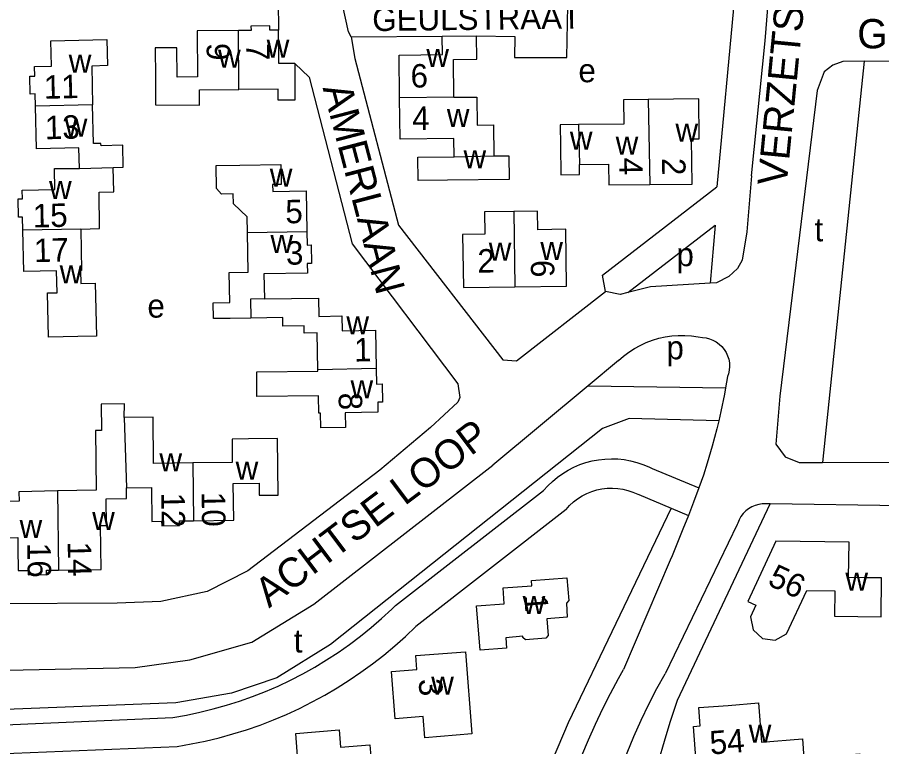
# Model space of a CAD drawing. Extents: x 156721 to 158827, y 386657 to 388950.
# Drawn here: x 158105.4 to 158252.9, y 387600.8 to 387725.3 of the extents above; entities that cross this region are included whole.
import ezdxf

# ---------------------------------------------------------------- set-up
doc = ezdxf.new("R2010")
doc.units = 0
for name, color, linetype in [('BLT_Basislijn', 7, 'Continuous'), ('BLT_Bebouwing', 7, 'Continuous'), ('BLT_Centroide', 7, 'Continuous'), ('BLT_Huisnummer', 7, 'Continuous'), ('BLT_Huisnummer_ tussenligend', 7, 'Continuous'), ('BLT_Onderverdeling_panden', 7, 'Continuous'), ('BLT_Straatnaam', 7, 'Continuous'), ('BLT_Straatnaam_verkleind', 7, 'Continuous')]:
    doc.layers.add(name, color=color, linetype=linetype)

msp = doc.modelspace()

# ---------------------------------------------------------------- linework, layer by layer
at = {"layer": 'BLT_Basislijn'}
for p, q in [((158229.04, 387741.65), (158224.79, 387696.34)), ((158149.92, 387727.95), (158149.97, 387723.07)), ((158162.37, 387721.93), (158177.92, 387722.06)), ((158249.95, 387717.76), (158242.83, 387649.3)), ((158152.75, 387717.41), (158155.18, 387715.03)), ((158155.18, 387715.03), (158162.54, 387686.61)), ((158205.28, 387681.26), (158224.79, 387696.34)), ((158209.61, 387678.29), (158224.52, 387689.81)), ((158224.52, 387689.81), (158223.65, 387679.92)), ((158162.54, 387686.61), (158180.58, 387662.74)), ((158205.81, 387678.51), (158205.28, 387681.26)), ((158208.02, 387666.72), (158202.82, 387662.39)), ((158226.63, 387663.98), (158226.28, 387662.04)), ((158180.58, 387662.74), (158180.9, 387660.42)), ((158202.82, 387662.39), (158186.53, 387648.84)), ((158202.82, 387662.39), (158226.28, 387662.04)), ((158180.9, 387660.42), (158180.58, 387659.62)), ((158180.58, 387659.62), (158175.92, 387655.3)), ((158175.92, 387655.3), (158167.26, 387648.03)), ((158213.75, 387648.27), (158221.71, 387644.99)), ((158167.26, 387648.03), (158144.75, 387630.82)), ((158222.52, 387647.14), (158221.71, 387644.99)), ((158169.91, 387624.92), (158195.21, 387644.52)), ((158211.46, 387643.83), (158216.97, 387641.54)), ((158218.09, 387608.76), (158233.87, 387642.27)), ((158233.87, 387642.27), (158233.18, 387642.28)), ((158270.59, 387641.69), (158233.87, 387642.27)), ((158199.05, 387641.32), (158173.42, 387621.35)), ((158216.97, 387641.54), (158207.52, 387621.83)), ((158216.97, 387641.54), (158219.93, 387640.3)), ((158228.28, 387638.75), (158215.94, 387613.27)), ((158216.84, 387632.65), (158208.88, 387613.99)), ((158144.75, 387630.82), (158137.79, 387627.31)), ((158137.79, 387627.31), (158129.87, 387625.61)), ((158122.4, 387625.3), (158078.39, 387625.06)), ((158129.87, 387625.61), (158122.4, 387625.3)), ((158207.52, 387621.83), (158199.39, 387604.87)), ((158093.22, 387604.12), (158131.92, 387605.82)), ((158199.39, 387604.87), (158196.7, 387598.46)), ((158095.31, 387599.32), (158132.68, 387600.88))]:
    msp.add_line(p, q, dxfattribs=at)
for points in [[(158230.7, 387698.25), (158233.04, 387721.24), (158234.67, 387741.75)], [(158162.37, 387721.93), (158161.92, 387722.8), (158160.89, 387727.45)], [(158183.78, 387722.13), (158190.28, 387721.98), (158190.27, 387718.43), (158199.18, 387718.42), (158199.34, 387727.31)], [(158162.37, 387721.93), (158162.99, 387718.25), (158170.46, 387689.82), (158188.23, 387666.84), (158190.61, 387666.68), (158205.81, 387678.51)], [(158249.95, 387717.76), (158246.27, 387717.74), (158244.57, 387717.09), (158243.09, 387715.96), (158241.94, 387712.8), (158235.53, 387660.62), (158234.87, 387652.44), (158236.45, 387650.27), (158238.86, 387649.33), (158242.83, 387649.3)], [(158331.61, 387684.16), (158329.92, 387691.11), (158327.69, 387713.57), (158325.62, 387716.63), (158322.75, 387717.43), (158319.65, 387717.59), (158249.95, 387717.76)], [(158230.7, 387698.25), (158229.92, 387688.65), (158229.12, 387683.83), (158228.32, 387682.39), (158226.84, 387681.07), (158224.73, 387679.99), (158223.65, 387679.92)], [(158331.61, 387684.16), (158330.27, 387682.97), (158337.29, 387598.34), (158342.49, 387594.21), (158431.88, 387594.8), (158432.5, 387594.66), (158434.94, 387592.24), (158434.85, 387566.34), (158432.92, 387555.36), (158430.15, 387548.17), (158421.36, 387530.67), (158420.31, 387528.76), (158417.02, 387526.27), (158293.15, 387534.97), (158290, 387537.72), (158280.9, 387649.05), (158280.63, 387649.25), (158242.83, 387649.3)], [(158223.65, 387679.92), (158213.47, 387679.26), (158209.61, 387678.29)], [(158209.61, 387678.29), (158208.3, 387677.96), (158205.81, 387678.51)], [(158208.02, 387666.72), (158208.88, 387667.46), (158209.78, 387668.14), (158210.72, 387668.76), (158211.71, 387669.3), (158212.74, 387669.77), (158213.79, 387670.17), (158214.87, 387670.5), (158215.97, 387670.74), (158217.09, 387670.91), (158218.21, 387671), (158219.34, 387671.01), (158220.47, 387670.93), (158221.59, 387670.78), (158222.32, 387670.64)], [(158222.32, 387670.64), (158222.94, 387670.57), (158223.55, 387670.42), (158224.13, 387670.19), (158224.68, 387669.89), (158225.19, 387669.52), (158225.64, 387669.1), (158226.04, 387668.61), (158226.37, 387668.08), (158226.63, 387667.52), (158226.82, 387666.92), (158226.93, 387666.3), (158226.96, 387665.68), (158226.91, 387665.05), (158226.78, 387664.44), (158226.63, 387663.98)], [(158226.28, 387662.04), (158226.09, 387660.99), (158225.47, 387658.01), (158225.1, 387656.4)], [(158225.1, 387656.4), (158209.8, 387656.83), (158205.26, 387655.11), (158158.86, 387618.27), (158149.7, 387612.59), (158141.94, 387609.97), (158132.46, 387608.3), (158098.96, 387606.99)], [(158225.1, 387656.4), (158224.78, 387655.05), (158224.01, 387652.1), (158223.16, 387649.18), (158222.52, 387647.14)], [(158195.21, 387644.52), (158195.94, 387645.34), (158196.74, 387646.1), (158197.58, 387646.8), (158198.48, 387647.44), (158199.42, 387648.02), (158200.39, 387648.52), (158201.4, 387648.95), (158202.45, 387649.31), (158203.51, 387649.59), (158204.59, 387649.79), (158205.68, 387649.91), (158206.78, 387649.95), (158207.88, 387649.92), (158208.98, 387649.8), (158210.06, 387649.6), (158211.12, 387649.33), (158212.16, 387648.98), (158213.18, 387648.55), (158213.75, 387648.27)], [(158095.39, 387613.72), (158125.49, 387614.36), (158134.85, 387615.64), (158145.39, 387618.65), (158155.99, 387625.14), (158186.53, 387648.84)], [(158199.05, 387641.32), (158199.65, 387641.98), (158200.32, 387642.59), (158201.03, 387643.13), (158201.79, 387643.61), (158202.59, 387644.03), (158203.43, 387644.37), (158204.29, 387644.63), (158205.17, 387644.82), (158206.06, 387644.92), (158206.96, 387644.95), (158207.86, 387644.9), (158208.75, 387644.77), (158209.62, 387644.56), (158210.47, 387644.27), (158211.3, 387643.91), (158211.46, 387643.83)], [(158221.71, 387644.99), (158220.8, 387642.52), (158219.93, 387640.3)], [(158233.18, 387642.28), (158232.55, 387642.27), (158231.93, 387642.17), (158231.33, 387642), (158230.76, 387641.75), (158230.22, 387641.43), (158229.72, 387641.04), (158229.28, 387640.6), (158228.9, 387640.1), (158228.59, 387639.55), (158228.35, 387638.98), (158228.28, 387638.75)], [(158219.93, 387640.3), (158219.01, 387637.94), (158217.15, 387633.38), (158216.84, 387632.65)], [(158131.92, 387605.82), (158134.24, 387606.22), (158136.54, 387606.7), (158138.83, 387607.26), (158141.09, 387607.89), (158143.33, 387608.6), (158145.55, 387609.38), (158147.74, 387610.24), (158149.9, 387611.18), (158152.03, 387612.18), (158154.12, 387613.26), (158156.17, 387614.41), (158158.18, 387615.63), (158160.15, 387616.92), (158162.08, 387618.27), (158163.96, 387619.69), (158165.79, 387621.17), (158167.56, 387622.71), (158169.29, 387624.31), (158169.91, 387624.92)], [(158132.68, 387600.88), (158135.08, 387601.29), (158137.47, 387601.78), (158139.84, 387602.35), (158142.19, 387603), (158144.51, 387603.72), (158146.81, 387604.52), (158149.09, 387605.39), (158151.33, 387606.34), (158153.55, 387607.36), (158155.72, 387608.46), (158157.86, 387609.62), (158159.96, 387610.85), (158162.02, 387612.16), (158164.04, 387613.52), (158166.01, 387614.96), (158167.93, 387616.46), (158169.8, 387618.02), (158171.62, 387619.64), (158173.42, 387621.35)], [(158194.39, 387559.31), (158194.4, 387562.23), (158194.49, 387565.15), (158194.67, 387568.07), (158194.92, 387570.98), (158195.25, 387573.88), (158195.66, 387576.78), (158196.15, 387579.66), (158196.73, 387582.52), (158197.37, 387585.37), (158198.1, 387588.21), (158198.9, 387591.01), (158199.78, 387593.8), (158200.74, 387596.56), (158201.77, 387599.3), (158202.87, 387602), (158204.05, 387604.68), (158205.3, 387607.32), (158206.63, 387609.92), (158208.02, 387612.49), (158208.88, 387613.99)], [(158201.24, 387552.3), (158201.17, 387555.33), (158201.17, 387558.37), (158201.24, 387561.4), (158201.4, 387564.43), (158201.64, 387567.45), (158201.96, 387570.47), (158202.36, 387573.48), (158202.84, 387576.47), (158203.4, 387579.46), (158204.03, 387582.42), (158204.74, 387585.37), (158205.54, 387588.3), (158206.4, 387591.21), (158207.35, 387594.09), (158208.37, 387596.95), (158209.46, 387599.77), (158210.63, 387602.57), (158211.87, 387605.34), (158213.19, 387608.07), (158214.57, 387610.77), (158215.94, 387613.27)], [(158210.06, 387568.18), (158210.28, 387571.59), (158210.58, 387574.99), (158210.96, 387578.39), (158211.43, 387581.78), (158211.96, 387585.15), (158212.58, 387588.51), (158213.28, 387591.85), (158214.06, 387595.18), (158214.91, 387598.49), (158215.84, 387601.78), (158216.84, 387605.04), (158217.93, 387608.28), (158218.09, 387608.76)]]:
    msp.add_lwpolyline(points, dxfattribs=at)
at = {"layer": 'BLT_Bebouwing'}
msp.add_line((158177.92, 387722.06), (158183.78, 387722.13), dxfattribs=at)
for points in [[(158149.97, 387723.07), (158148.47, 387723.06), (158148.46, 387723.8), (158145.27, 387723.78), (158145.28, 387723.02), (158143.14, 387723)], [(158143.14, 387723), (158136.1, 387722.96), (158136.14, 387715.09), (158132.65, 387715.07), (158132.62, 387720.08), (158128.93, 387720.06), (158128.95, 387715.06), (158128.98, 387710.33)], [(158152.75, 387717.41), (158150.01, 387717.39), (158149.97, 387723.07)], [(158170.64, 387711.51), (158170.55, 387718.83), (158177.96, 387718.92), (158177.92, 387722.06)], [(158179.9, 387711.63), (158179.82, 387718.06), (158183.83, 387718.11), (158183.78, 387722.13)], [(158108.46, 387710.1), (158108.41, 387712.2), (158107.6, 387712.18), (158107.53, 387715.23), (158108.36, 387715.25), (158108.32, 387716.87), (158111.22, 387716.94), (158111.12, 387721.26), (158120.67, 387721.49)], [(158120.67, 387721.49), (158120.78, 387717.02), (158118.09, 387716.95), (158118.24, 387710.34)], [(158152.75, 387717.41), (158152.78, 387711.13), (158149.92, 387711.11), (158149.91, 387712.99), (158143.2, 387712.95)], [(158128.98, 387710.33), (158136.49, 387710.28), (158136.48, 387712.91), (158143.2, 387712.95)], [(158179.9, 387711.63), (158183.82, 387711.67), (158183.87, 387706.88), (158186.68, 387706.91), (158186.74, 387701.63)], [(158115.98, 387699.49), (158115.9, 387702.99), (158108.63, 387702.82), (158108.46, 387710.1)], [(158121.77, 387699.67), (158123.46, 387699.71), (158123.37, 387703.43), (158119.67, 387703.34), (158119.66, 387703.75), (158118.4, 387703.72), (158118.24, 387710.34)], [(158179.95, 387701.47), (158179.91, 387704.58), (158170.72, 387704.47), (158170.64, 387711.51)], [(158213.07, 387711.26), (158208.85, 387711.21), (158208.89, 387707.04), (158201.16, 387706.96)], [(158213.33, 387696.73), (158220.55, 387696.81), (158220.46, 387704.53), (158221.76, 387704.54), (158221.69, 387711.35), (158213.07, 387711.26)], [(158201.16, 387706.96), (158198.05, 387706.93), (158198.08, 387703.4), (158198.14, 387698.4), (158201.37, 387698.43), (158201.36, 387700.15)], [(158186.74, 387701.63), (158189.3, 387701.66), (158189.35, 387697.59), (158178.79, 387697.46), (158173.79, 387697.4), (158173.74, 387701.4), (158179.95, 387701.47)], [(158139.33, 387699.96), (158143.36, 387700.04), (158150.36, 387700.17), (158150.42, 387696.77), (158148.96, 387696.75), (158148.98, 387695.55), (158154.69, 387695.64), (158154.81, 387688.74)], [(158144.66, 387688.57), (158144.61, 387691.21), (158142.28, 387693.43), (158142.25, 387695.14), (158140.23, 387695.09), (158139.36, 387696.04), (158139.33, 387699.96)], [(158201.36, 387700.15), (158206.31, 387700.2), (158206.35, 387696.66), (158213.33, 387696.73)], [(158106.34, 387688.96), (158106.29, 387691.18), (158105.57, 387691.16), (158105.5, 387694.28), (158106.25, 387694.3), (158106.22, 387695.77), (158111.81, 387695.9), (158111.73, 387699.49), (158115.98, 387699.49)], [(158119.33, 387695.46), (158121.87, 387695.52), (158121.77, 387699.67)], [(158116.24, 387689.1), (158119.43, 387689.22), (158119.33, 387695.46)], [(158190.16, 387692.13), (158185.12, 387692.09), (158185.18, 387688.29), (158181.4, 387688.23), (158181.53, 387679.17), (158190.33, 387679.29)], [(158190.33, 387679.29), (158199.12, 387679.41), (158198.99, 387689.1), (158194.24, 387689.03), (158194.19, 387692.21), (158190.16, 387692.13)], [(158118.88, 387670.86), (158115.72, 387670.79), (158110.72, 387670.67), (158110.54, 387678.24), (158112.17, 387678.28), (158112.08, 387682.04), (158106.51, 387681.91), (158106.34, 387688.96)], [(158116.24, 387689.1), (158116.36, 387682.1)], [(158141.61, 387679.16), (158141.57, 387681.74), (158144.77, 387681.8), (158144.66, 387688.57)], [(158154.81, 387688.74), (158154.85, 387686.42), (158155.56, 387686.43), (158155.62, 387683.29), (158154.86, 387683.28), (158154.89, 387681.64), (158147.49, 387681.52), (158147.56, 387677.25)], [(158116.36, 387682.1), (158116.16, 387682.1), (158116.2, 387679.87)], [(158116.2, 387679.87), (158118.69, 387679.91), (158118.88, 387670.86)], [(158145.26, 387673.96), (158141.7, 387673.9), (158138.87, 387673.88), (158138.82, 387676.56), (158141.65, 387676.61), (158141.61, 387679.16)], [(158147.56, 387677.25), (158156.78, 387677.38), (158156.84, 387674.24), (158160.77, 387674.32), (158160.82, 387671.79), (158166.51, 387671.91), (158166.64, 387665.33)], [(158156.7, 387665.13), (158156.57, 387671.43), (158154.35, 387671.39), (158154.32, 387672.62), (158150.72, 387672.55), (158150.7, 387674.05), (158145.25, 387673.96)], [(158157.19, 387655.22), (158157.14, 387657.75), (158156.85, 387657.74), (158156.79, 387660.67), (158146.27, 387660.59), (158146.24, 387664.79), (158156.7, 387664.92)], [(158156.7, 387664.92), (158156.7, 387665.13)], [(158166.64, 387665.33), (158166.7, 387662.69), (158167.66, 387662.71), (158167.73, 387659.61), (158166.9, 387659.59), (158166.93, 387657.9), (158161.33, 387657.79), (158161.38, 387655.3), (158157.19, 387655.22)], [(158123.61, 387657.01), (158123.7, 387659.3), (158119.7, 387659.26), (158119.75, 387654.79), (158118.73, 387654.78), (158118.84, 387644.57), (158112.23, 387644.46)], [(158135.36, 387649.25), (158128.64, 387649.17), (158128.55, 387657.07), (158123.61, 387657.01)], [(158149.82, 387653.4), (158144.82, 387653.34), (158142.03, 387653.31), (158142.08, 387649.33), (158135.36, 387649.25)], [(158135.47, 387639.38), (158142.32, 387639.46), (158142.25, 387645.71), (158146.65, 387645.76), (158146.67, 387643.72), (158149.93, 387643.75), (158149.82, 387653.4)], [(158112.23, 387644.46), (158105.65, 387644.32), (158105.67, 387642.69), (158100.92, 387642.62), (158100.88, 387645.26), (158099.06, 387645.23), (158099.1, 387642.59)], [(158112.43, 387630.96), (158119.71, 387631.07), (158119.59, 387638.57), (158120.6, 387638.58), (158120.53, 387643.14), (158124.02, 387643.18), (158124, 387644.99)], [(158124, 387644.99), (158128.27, 387645.04), (158128.33, 387639.26), (158130.02, 387639.28), (158130.03, 387638.51), (158133.07, 387638.54), (158133.06, 387639.35), (158135.47, 387639.38)], [(158099.19, 387636.91), (158099.21, 387634.58), (158103.28, 387634.64), (158103.25, 387636.47), (158105.47, 387636.5), (158105.49, 387634.7), (158105.55, 387630.87), (158107.25, 387630.9), (158107.26, 387630.16), (158110.36, 387630.21), (158110.35, 387630.93), (158112.43, 387630.96)], [(158252.83, 387622.99), (158252.89, 387629.62), (158250.4, 387629.65), (158247.29, 387629.68), (158247.36, 387635.71), (158234.85, 387635.87), (158230.09, 387625.62), (158231.47, 387624.98), (158230.54, 387623), (158230.98, 387620.77), (158232.56, 387619.31), (158234.76, 387619.03), (158236.67, 387620.1), (158240.14, 387627.46), (158244.95, 387627.4), (158244.9, 387623.08), (158252.83, 387622.99)], [(158188.3, 387627.91), (158193.23, 387628.29), (158193.15, 387629.16), (158199.21, 387629.63), (158199.54, 387625.75), (158199.1, 387625.29), (158199.26, 387622.95), (158195.77, 387622.67), (158196, 387619.77), (158195.62, 387619.35), (158192.14, 387619.07), (158191.69, 387619.46), (158191.65, 387619.66), (158188.75, 387619.38), (158188.9, 387617.65), (158184.37, 387617.29), (158183.79, 387624.85), (158188.5, 387625.2), (158188.3, 387627.91)], [(158169.28, 387613.66), (158173.6, 387613.98), (158173.42, 387616.36), (158181.91, 387617), (158182.97, 387603), (158174.96, 387602.36), (158174.66, 387605.97), (158169.9, 387605.6), (158169.28, 387613.66)], [(158227.54, 387597.91), (158222.56, 387597.5), (158222.49, 387598.3), (158221.28, 387598.2), (158220.78, 387604.3), (158221.97, 387604.39), (158221.73, 387607.49), (158226.71, 387607.88), (158231.89, 387608.29), (158232.42, 387601.61), (158239.39, 387602.16), (158239.65, 387598.87), (158249.2, 387599.61), (158249.35, 387596.13)], [(158152.9, 387603.09), (158160.33, 387603.68), (158160.57, 387600.72), (158165.58, 387601.12), (158166.18, 387593.64), (158161.16, 387593.24), (158161.3, 387591.46), (158153.86, 387590.87), (158152.9, 387603.09)]]:
    msp.add_lwpolyline(points, dxfattribs=at)
at = {"layer": 'BLT_Onderverdeling_panden'}
for p, q in [((158143.2, 387712.95), (158143.14, 387723)), ((158179.9, 387711.63), (158170.64, 387711.51)), ((158118.24, 387710.34), (158108.46, 387710.1)), ((158213.07, 387711.26), (158213.33, 387696.73)), ((158201.16, 387706.96), (158201.36, 387700.15)), ((158179.95, 387701.47), (158186.74, 387701.63)), ((158115.98, 387699.49), (158121.77, 387699.67)), ((158190.16, 387692.13), (158190.33, 387679.29)), ((158116.24, 387689.1), (158106.34, 387688.96)), ((158144.66, 387688.57), (158154.81, 387688.74)), ((158166.64, 387665.33), (158156.7, 387665.13)), ((158123.61, 387657.01), (158124, 387644.99)), ((158135.36, 387649.25), (158135.47, 387639.38)), ((158112.23, 387644.46), (158112.43, 387630.96))]:
    msp.add_line(p, q, dxfattribs=at)
msp.add_lwpolyline([(158147.56, 387677.25), (158145.2, 387677.2), (158145.26, 387673.96)], dxfattribs=at)

# ---------------------------------------------------------------- texts
at = {"layer": 'BLT_Centroide'}
for s, p in [('w', (158147.95, 387718.38)), ('w', (158139.65, 387716.66)), ('w', (158175.2, 387716.81)), ('w', (158114.16, 387715.8)), ('e', (158201.16, 387714.19)), ('w', (158178.7, 387706.56)), ('w', (158113.48, 387704.91)), ('w', (158199.7, 387702.67)), ('w', (158217.72, 387704.05)), ('w', (158207.52, 387701.84)), ('w', (158181.55, 387699.53)), ('w', (158148.48, 387696.38)), ('w', (158110.8, 387694.28)), ('t', (158241.46, 387687.05)), ('w', (158148.59, 387685.08)), ('w', (158185.86, 387683.75)), ('w', (158194.66, 387683.88)), ('p', (158217.89, 387682.81)), ('w', (158112.61, 387679.88)), ('e', (158127.59, 387674.03)), ('w', (158161.55, 387671.16)), ('p', (158216.18, 387666.92)), ('w', (158162.26, 387660.28)), ('w', (158129.64, 387647.78)), ('w', (158142.65, 387646.38)), ('w', (158118.16, 387637.8)), ('w', (158105.77, 387636.44)), ('w', (158246.73, 387627.44)), ('w', (158191.64, 387623.47)), ('t', (158152.56, 387616.89)), ('w', (158176.03, 387609.69)), ('w', (158230.23, 387601.5))]:
    msp.add_text(s, height=4, dxfattribs=at).set_placement(p)
at = {"layer": 'BLT_Huisnummer'}
for s, rotation, p in [('9', 270.3273, (158137.7, 387720.87)), ('7', 270.3247, (158144.44, 387720.87)), ('6', 0.6928, (158172.53, 387713.27)), ('11', 1.3577, (158109.96, 387711.36)), ('4', 0.695, (158172.8, 387706.03)), ('4', 270.6302, (158208.1, 387701.31)), ('2', 270.629, (158215.43, 387701.25)), ('5', 0.965, (158151.17, 387690.11)), ('17', 1.3637, (158108.26, 387683.49)), ('2', 0.8011, (158183.94, 387681.7)), ('6', 270.8026, (158193.03, 387683.85)), ('1', 1.1576, (158162.9, 387666.53)), ('8', 271.1575, (158160.22, 387661.19)), ('10', 270.6557, (158136.85, 387644.28)), ('14', 270.8632, (158113.98, 387635.79)), ('56', 335.1196, (158233.27, 387628.49)), ('1', 274.5178, (158191.88, 387626.67)), ('3', 274.2902, (158173.86, 387612.31)), ('54', 4.3089, (158223.71, 387599.48))]:
    msp.add_text(s, height=4, rotation=rotation, dxfattribs=at).set_placement(p)
at = {"layer": 'BLT_Huisnummer_ tussenligend'}
for s, rotation, p in [('13', 1.3636, (158110.13, 387704.45)), ('15', 1.3664, (158108.07, 387689.4)), ('3', 0.9638, (158151.27, 387683.05)), ('12', 270.6534, (158129.96, 387644.16)), ('16', 270.8522, (158107.08, 387635.58))]:
    msp.add_text(s, height=4, rotation=rotation, dxfattribs=at).set_placement(p)
at = {"layer": 'BLT_Straatnaam'}
for s, rotation, p in [('VERZETSHELDENLAAN', 84.4521, (158236.69, 387696.35)), ('GEBROEDERS GANSLAAN', 359.5846, (158248.74, 387719.99)), ('AMERLAAN', 284.6774, (158157.48, 387713.24)), ('ACHTSE LOOP', 36.9962, (158148.35, 387624.4))]:
    msp.add_text(s, height=5, rotation=rotation, dxfattribs=at).set_placement(p)
at = {"layer": 'BLT_Straatnaam_verkleind'}
msp.add_text('GEULSTRAAT', height=4, rotation=0.7158, dxfattribs=at).set_placement((158165.99, 387722.91))

doc.saveas('drawing.dxf')
